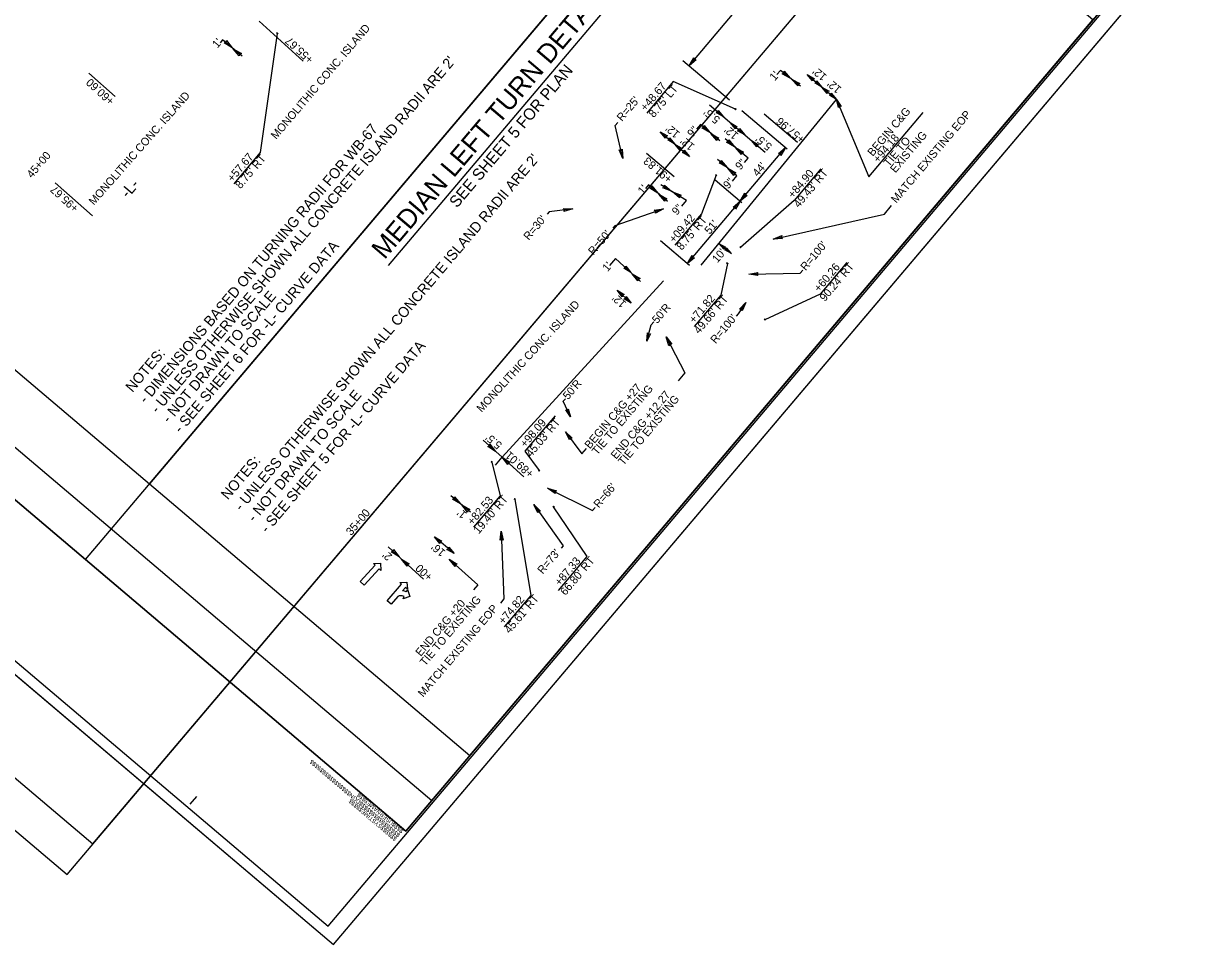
# Model space of a CAD drawing. Extents: x 1763138 to 1764249, y 424045 to 425159.
# Drawn here: x 1763511 to 1764249, y 424122 to 424697 of the extents above; entities that cross this region are included whole.
import ezdxf

# ---------------------------------------------------------------- set-up
doc = ezdxf.new("R2010")
doc.units = 0
for name, color, linetype in [('Default', 7, 'Continuous'), ('Old_Level_11', 7, 'Continuous'), ('Prop Conc 2ft 6in Curb and Gutter', 7, 'Continuous'), ('Prop Dimension Text', 7, 'Continuous'), ('Prop Grid Mask', 7, 'Continuous'), ('Prop Horizontal Alignment Station Label', 7, 'Continuous'), ('Scratch_Level_0', 7, 'Continuous'), ('Sheet Block Revision CELL', 7, 'Continuous'), ('Sheet Clip Boundary CELL', 7, 'Continuous'), ('Sheet Cutting Line CELL', 7, 'Continuous'), ('Sheet Data Field CELL', 7, 'Continuous'), ('Sheet Plan Layout CELL', 7, 'Continuous'), ('Sheet Plot Border Inside CELL', 7, 'Continuous'), ('Sheet Sticker Exception Certification CELL', 7, 'Continuous'), ('Sheet Title CELL', 7, 'Continuous')]:
    doc.layers.add(name, color=color, linetype=linetype)

# ---------------------------------------------------------------- blocks, each defined once
blk = doc.blocks.new('Terminator')
at = {"layer": 'Old_Level_11'}
blk.add_lwpolyline([(-9, 1.55), (0, 0), (-9.05, -1.6), (-7.9, 0)], close=True, dxfattribs=at)

msp = doc.modelspace()

# ---------------------------------------------------------------- linework, layer by layer
at = {"layer": 'Old_Level_11'}
for points in [[(1763637.67, 424686.67), (1763641.21, 424682.13), (1763636.31, 424685.22), (1763637.52, 424685.48)], [(1763645.7, 424677.1), (1763641.97, 424681.49), (1763646.99, 424678.6), (1763645.79, 424678.29)], [(1763994.59, 424658.35), (1763990.74, 424662.62), (1763995.84, 424659.89), (1763994.65, 424659.54)], [(1764003.93, 424661.47), (1764000.6, 424665.44), (1764005.1, 424662.81), (1764004.02, 424662.54)], [(1764006.43, 424661.65), (1764009.76, 424657.68), (1764005.26, 424660.31), (1764006.34, 424660.58)], [(1764013.08, 424653.71), (1764009.76, 424657.68), (1764014.26, 424655.06), (1764013.18, 424654.79)], [(1764015.59, 424653.89), (1764018.91, 424649.93), (1764014.41, 424652.55), (1764015.5, 424652.82)], [(1764020.06, 424644.88), (1764018.91, 424649.93), (1764021.72, 424645.54), (1764020.63, 424645.79)], [(1763944.81, 424643.06), (1763948.14, 424639.09), (1763943.64, 424641.72), (1763944.72, 424641.99)], [(1763955.66, 424631.57), (1763952.33, 424635.54), (1763956.84, 424632.91), (1763955.75, 424632.64)], [(1763912.08, 424625.76), (1763908.76, 424629.73), (1763913.26, 424627.11), (1763912.17, 424626.84)], [(1763914.59, 424625.95), (1763917.91, 424621.98), (1763913.41, 424624.6), (1763914.49, 424624.87)], [(1763944.02, 424624.3), (1763940.32, 424628.71), (1763945.33, 424625.79), (1763944.12, 424625.49)], [(1763958.16, 424631.75), (1763961.49, 424627.78), (1763956.99, 424630.4), (1763958.07, 424630.67)], [(1763921.24, 424618.01), (1763917.91, 424621.98), (1763922.41, 424619.35), (1763921.33, 424619.08)], [(1763923.74, 424618.19), (1763927.07, 424614.22), (1763922.57, 424616.84), (1763923.65, 424617.12)], [(1763959.46, 424615.45), (1763955.77, 424619.86), (1763960.77, 424616.94), (1763959.56, 424616.64)], [(1763969.01, 424620.26), (1763965.69, 424624.22), (1763970.19, 424621.6), (1763969.1, 424621.33)], [(1763946.74, 424611.8), (1763950.44, 424607.39), (1763945.44, 424610.3), (1763946.64, 424610.6)], [(1763954.71, 424602.49), (1763951.01, 424606.9), (1763956.01, 424603.99), (1763954.81, 424603.68)], [(1763911.41, 424596.33), (1763915.75, 424592.56), (1763910.35, 424594.65), (1763911.49, 424595.14)], [(1763911.51, 424586.3), (1763907.88, 424590.77), (1763912.84, 424587.78), (1763911.63, 424587.49)], [(1763920.73, 424588.39), (1763916.39, 424592.17), (1763921.78, 424590.07), (1763920.64, 424589.58)], [(1763905, 424580.71), (1763910.67, 424581.69), (1763905.64, 424578.83), (1763905.98, 424580.02)], [(1763948.45, 424556.45), (1763945.39, 424559.97), (1763949.49, 424557.68), (1763948.52, 424557.42)], [(1763950.08, 424557.16), (1763953.14, 424553.64), (1763949.05, 424555.93), (1763950.02, 424556.19)], [(1763887.26, 424545.85), (1763890.43, 424541.76), (1763886.03, 424544.55), (1763887.13, 424544.78)], [(1763894.7, 424536.54), (1763891.17, 424541.08), (1763896.06, 424537.98), (1763894.84, 424537.73)], [(1763884.91, 424526.69), (1763881.74, 424530.78), (1763886.14, 424527.99), (1763885.04, 424527.76)], [(1763887.42, 424526.78), (1763890.59, 424522.68), (1763886.19, 424525.48), (1763887.29, 424525.71)], [(1763902.56, 424503.59), (1763900.4, 424498.89), (1763900.84, 424504.08), (1763901.55, 424503.22)], [(1763851.27, 424456.68), (1763852.61, 424451.68), (1763849.64, 424455.96), (1763850.73, 424455.75)], [(1763813.4, 424421.83), (1763809.87, 424426.38), (1763814.76, 424423.27), (1763813.54, 424423.01)], [(1763780.19, 424401.65), (1763783.88, 424397.24), (1763778.88, 424400.16), (1763780.09, 424400.46)], [(1763788.35, 424392.19), (1763784.65, 424396.6), (1763789.65, 424393.69), (1763788.45, 424393.39)], [(1763771.04, 424372.64), (1763767.71, 424376.61), (1763772.22, 424373.99), (1763771.13, 424373.72)], [(1763776.6, 424370.24), (1763779.92, 424366.27), (1763775.42, 424368.89), (1763776.5, 424369.17)], [(1763750.5, 424358.31), (1763746.97, 424362.85), (1763751.86, 424359.75), (1763750.64, 424359.5)]]:
    msp.add_lwpolyline(points, close=True, dxfattribs=at)
at = {"layer": 'Prop Conc 2ft 6in Curb and Gutter'}
for p, q in [((1763729.58, 424360.03), (1763733.99, 424360.25)), ((1763730.68, 424359.01), (1763729.58, 424360.03)), ((1763733.99, 424360.25), (1763734.21, 424355.76)), ((1763721.21, 424348.71), (1763730.68, 424359.01)), ((1763733.11, 424356.78), (1763723.63, 424346.47)), ((1763734.21, 424355.76), (1763733.11, 424356.78)), ((1763723.63, 424346.47), (1763721.21, 424348.71)), ((1763738.09, 424336.81), (1763747.14, 424347.22)), ((1763746.01, 424348.21), (1763750.42, 424348.48)), ((1763747.14, 424347.22), (1763746.01, 424348.21)), ((1763749.63, 424345.06), (1763747.76, 424342.91)), ((1763750.76, 424344.07), (1763749.63, 424345.06)), ((1763750.42, 424348.48), (1763750.76, 424344.07)), ((1763744.81, 424339.51), (1763740.58, 424334.65)), ((1763752.18, 424339.53), (1763747.99, 424338.07)), ((1763747.99, 424338.07), (1763748.61, 424339.39)), ((1763750.07, 424342.36), (1763750.72, 424343.72)), ((1763750.72, 424343.72), (1763752.18, 424339.53)), ((1763740.58, 424334.65), (1763738.09, 424336.81))]:
    msp.add_line(p, q, dxfattribs=at)
for centre, radius, start, end in [((1763746.23, 424337.43), 2.52, 88.0631, 124.3751), ((1763746.44, 424335.52), 4.43, 60.69963, 91.55318), ((1763747.88, 424338.49), 4.43, 60.58082, 91.45941)]:
    msp.add_arc(centre, radius, start, end, dxfattribs=at)
at = {"layer": 'Prop Grid Mask'}
msp.add_line((1763738.82, 424546.17), (1763881.32, 424714.38), dxfattribs=at)
at = {"layer": 'Prop Horizontal Alignment Station Label'}
for p, q in [((1763934.24, 424546.32), (1764018.91, 424649.93)), ((1763809.87, 424426.38), (1763910.78, 424536.59)), ((1763805.71, 424421.47), (1763809.87, 424426.38))]:
    msp.add_line(p, q, dxfattribs=at)
at = {"layer": 'Sheet Block Revision CELL'}
for points in [[(1763765.97, 424212), (1764218.44, 424746.11), (1763898.55, 425017.11), (1763837.38, 424944.91), (1763756.7, 425013.26), (1763365.39, 424551.35)], [(1763554.26, 424184.86), (1764006.73, 424718.97), (1763686.84, 424989.97), (1763625.67, 424917.77), (1763544.99, 424986.12), (1763153.68, 424524.22)]]:
    msp.add_lwpolyline(points, close=True, dxfattribs=at)
at = {"layer": 'Sheet Clip Boundary CELL'}
for p, q in [((1763704.59, 424122.13), (1764248.69, 424764.39)), ((1763286.84, 424476.03), (1763704.59, 424122.13))]:
    msp.add_line(p, q, dxfattribs=at)
at = {"layer": 'Sheet Cutting Line CELL'}
for points in [[(1763349.23, 424532.26), (1763749.81, 424192.92), (1764234.6, 424765.18), (1763914.7, 425036.18), (1763837.38, 424944.91), (1763756.7, 425013.26)], [(1763137.52, 424505.12), (1763538.1, 424165.79), (1764022.89, 424738.04), (1763702.99, 425009.04), (1763625.67, 424917.77), (1763544.99, 424986.12)]]:
    msp.add_lwpolyline(points, close=True, dxfattribs=at)
at = {"layer": 'Sheet Data Field CELL'}
for p, q in [((1763615.03, 424209.8), (1763619.08, 424214.57)), ((1763749.81, 424192.92), (1763749.81, 424192.92))]:
    msp.add_line(p, q, dxfattribs=at)
for points in [[(1763834.03, 425104.55), (1763349.23, 424532.28), (1763749.81, 424192.92), (1764234.6, 424765.18)], [(1763749.81, 424192.92), (1763349.23, 424532.26), (1763769.36, 425028.22), (1763826.62, 424979.73), (1763891.27, 425056.04), (1764234.6, 424765.18)]]:
    msp.add_lwpolyline(points, close=True, dxfattribs=at)
at = {"layer": 'Sheet Plan Layout CELL'}
msp.add_lwpolyline([(1763701.16, 424133.55), (1764239.59, 424769.14), (1763837.12, 425110.11), (1763298.67, 424474.52)], close=True, dxfattribs=at)
at = {"layer": 'Sheet Plot Border Inside CELL'}
msp.add_lwpolyline([(1763704.59, 424122.13), (1764248.69, 424764.39), (1763830.94, 425118.29), (1763286.84, 424476.03)], close=True, dxfattribs=at)
at = {"layer": 'Sheet Sticker Exception Certification CELL'}
for points in [[(1763589.54, 424409.85), (1763969.1, 424857.88), (1763768.81, 425027.56), (1763389.25, 424579.52)], [(1763789.83, 424240.17), (1764179.09, 424699.66), (1763978.81, 424869.34), (1763589.54, 424409.85)]]:
    msp.add_lwpolyline(points, close=True, dxfattribs=at)
at = {"layer": 'Sheet Title CELL'}
for p, q in [((1763549.51, 424362.59), (1764034.31, 424934.86)), ((1763926.69, 424671.02), (1764030.12, 424793.1)), ((1763658.14, 424698.8), (1763685.56, 424673.78)), ((1763669.88, 424690.82), (1763669.01, 424691.56)), ((1763669.77, 424691.58), (1763669.12, 424690.8)), ((1763922.85, 424674.27), (1763951.96, 424649.61)), ((1763551.71, 424666.44), (1763568.05, 424651.81)), ((1764000.6, 424665.44), (1764018.91, 424649.93)), ((1763939.4, 424646.5), (1763974.21, 424617)), ((1763956.16, 424643.43), (1763955.3, 424644.16)), ((1763956.06, 424644.18), (1763955.4, 424643.41)), ((1763959.71, 424643.05), (1763987.91, 424619.15)), ((1763973.56, 424640.87), (1763994.39, 424623.22)), ((1763908.76, 424629.73), (1763927.07, 424614.22)), ((1763958.62, 424586.3), (1763987.06, 424619.88)), ((1763900.22, 424616.34), (1763917.47, 424601.73)), ((1763944.14, 424602.17), (1763943.28, 424602.9)), ((1763944.04, 424602.92), (1763943.38, 424602.15)), ((1763530.56, 424597.85), (1763553.92, 424577.28)), ((1763959.64, 424585.44), (1763942.92, 424599.6)), ((1763925.65, 424547.39), (1763958.62, 424586.3)), ((1763926.94, 424546.3), (1763908.85, 424561.63)), ((1763945.39, 424559.97), (1763953.14, 424553.64)), ((1763959.34, 424557.17), (1763958.47, 424557.9)), ((1763959.23, 424557.92), (1763958.57, 424557.14)), ((1763951.06, 424547.04), (1763950.19, 424547.77)), ((1763950.95, 424547.79), (1763950.29, 424547.01)), ((1763890.59, 424522.68), (1763881.74, 424530.78)), ((1763974.55, 424511.99), (1763973.68, 424512.72)), ((1763974.44, 424512.74), (1763973.79, 424511.97)), ((1763809.87, 424426.38), (1763798.1, 424437.16)), ((1763823.46, 424414.27), (1763809.87, 424426.38)), ((1763803.86, 424423.04), (1763802.99, 424423.77)), ((1763803.75, 424423.79), (1763803.09, 424423.01)), ((1763833.41, 424417.7), (1763832.54, 424418.43)), ((1763833.3, 424418.45), (1763832.65, 424417.67)), ((1763818.25, 424399.81), (1763817.39, 424400.54)), ((1763818.15, 424400.56), (1763817.49, 424399.78)), ((1763842.48, 424395.13), (1763841.61, 424395.86)), ((1763842.37, 424395.88), (1763841.71, 424395.11)), ((1763779.92, 424366.27), (1763767.71, 424376.61)), ((1763738.73, 424370.4), (1763760.8, 424350.19))]:
    msp.add_line(p, q, dxfattribs=at)
for points in [[(1763647.42, 424676.93), (1763635.24, 424687.11), (1763633.77, 424685.37)], [(1763669.45, 424691.19), (1763658.82, 424616.84), (1763642.2, 424597.22)], [(1763996.32, 424658.23), (1763983.85, 424668.05), (1763981.62, 424665.41)], [(1763955.73, 424643.8), (1763916.85, 424661.04), (1763900.23, 424641.43)], [(1764018.91, 424649.93), (1764039.02, 424601.53), (1764073.04, 424641.69)], [(1763885.34, 424613.05), (1763880.53, 424633.59), (1763882.11, 424635.45)], [(1763945.85, 424624.03), (1763933.82, 424634.22), (1763931.39, 424631.34)], [(1763961.26, 424610.45), (1763963.61, 424613.22), (1763949.26, 424625.37)], [(1763953.93, 424598.98), (1763956.62, 424602.15), (1763944.51, 424612.41)], [(1764008.95, 424606.51), (1763992.33, 424586.89), (1763958.9, 424557.53)], [(1763913.23, 424586.1), (1763901.27, 424596.53), (1763899.42, 424594.35)], [(1763922.18, 424583.29), (1763925.18, 424586.83), (1763909.1, 424596.59)], [(1763943.71, 424602.54), (1763934.49, 424578.46), (1763917.87, 424558.84)], [(1763854.05, 424581.65), (1763839.32, 424579.65), (1763838.08, 424578.19)], [(1763910.67, 424581.69), (1763880.29, 424570.89), (1763879.05, 424569.42)], [(1763979.3, 424562.67), (1764048.75, 424578.33), (1764053.23, 424583.63)], [(1763896.41, 424536.29), (1763880.68, 424550.65), (1763876.98, 424546.28)], [(1763950.63, 424547.41), (1763946.61, 424527.69), (1763929.99, 424508.07)], [(1764025.22, 424547.99), (1764008.6, 424528.37), (1763974.12, 424512.36)], [(1763964.08, 424540.79), (1763996.19, 424541.4), (1763997.77, 424543.26)], [(1763962.24, 424523.06), (1763957.45, 424516.09), (1763956.21, 424514.63)], [(1763900.4, 424498.89), (1763903.1, 424509.07), (1763904.76, 424511.03)], [(1763912.35, 424501.56), (1763924.13, 424479.11), (1763919.97, 424474.2)], [(1763852.61, 424451.68), (1763848.11, 424461.41), (1763849.45, 424462.99)], [(1763842.97, 424452.32), (1763824.19, 424430.15), (1763832.98, 424418.07)], [(1763849.44, 424442.39), (1763859.77, 424428.62), (1763862.61, 424431.97)], [(1763803.42, 424423.4), (1763808.59, 424402.29), (1763791.97, 424382.67)], [(1763838.35, 424407.12), (1763866.44, 424393.14), (1763868.02, 424395)], [(1763790.07, 424392.02), (1763777.95, 424402.26)], [(1763817.82, 424400.18), (1763827.87, 424340.13), (1763811.25, 424320.51)], [(1763829.75, 424396.88), (1763848.08, 424371.08), (1763846.85, 424369.62)], [(1763845.18, 424343.15), (1763863.13, 424364.33), (1763842.04, 424395.5)], [(1763809.35, 424380.24), (1763811.04, 424337.89), (1763808.83, 424335.28)], [(1763776.92, 424362.71), (1763794.68, 424346.75), (1763792.01, 424343.59)]]:
    msp.add_lwpolyline(points, dxfattribs=at)

# ---------------------------------------------------------------- block references
at = {"layer": 'Default'}
for p, xscale, yscale, rotation in [((1763926.69, 424671.02), 0.6300000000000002, 0.6299999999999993, -130.26989656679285), ((1763989.96, 424663.24), 0.6300000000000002, 0.6299999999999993, -38.216341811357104), ((1763939.75, 424629.19), 0.6300000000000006, 0.6299999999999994, -40.269896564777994), ((1763885.34, 424613.05), 0.6300000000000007, 0.6299999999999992, -76.80801773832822), ((1763955.19, 424620.35), 0.6300000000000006, 0.6299999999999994, -40.269896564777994), ((1763987.06, 424619.88), 0.6300000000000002, 0.6299999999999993, 49.73010343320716), ((1763907.13, 424591.42), 0.6300000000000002, 0.6299999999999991, -41.09557866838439), ((1763958.62, 424586.3), 0.6300000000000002, 0.6299999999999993, -130.26989656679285), ((1763854.05, 424581.65), 0.6299999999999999, 0.6299999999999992, 7.706806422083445), ((1763958.62, 424586.3), 0.6300000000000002, 0.6299999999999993, 49.73010343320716), ((1763979.3, 424562.67), 0.6300000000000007, 0.6299999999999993, -167.28779310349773), ((1763925.65, 424547.39), 0.6300000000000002, 0.6299999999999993, -130.26989656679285), ((1763964.08, 424540.79), 0.6300000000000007, 0.6299999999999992, -178.90669150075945), ((1763962.24, 424523.06), 0.6300000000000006, 0.6299999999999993, 55.467364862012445), ((1763912.35, 424501.56), 0.630000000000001, 0.6299999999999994, 117.68870627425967), ((1763849.44, 424442.39), 0.6300000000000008, 0.6299999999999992, 126.89575304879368), ((1763805.82, 424430.09), 0.6300000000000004, 0.6299999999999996, -42.4765986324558), ((1763838.35, 424407.12), 0.6300000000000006, 0.6299999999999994, 153.5465740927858), ((1763829.75, 424396.88), 0.6300000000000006, 0.6299999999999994, 125.40671690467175), ((1763809.35, 424380.24), 0.6300000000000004, 0.6299999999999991, 92.2799832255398), ((1763745.49, 424364.2), 0.6300000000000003, 0.629999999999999, -42.391811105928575), ((1763776.92, 424362.71), 0.6300000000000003, 0.6299999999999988, 138.05302793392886)]:
    msp.add_blockref('Terminator', p, dxfattribs=dict(at, xscale=xscale, yscale=yscale, rotation=rotation))

# ---------------------------------------------------------------- texts
at = {"layer": 'Prop Dimension Text'}
for s, height, rotation, p in [('MEDIAN LEFT TURN DETAIL', 12, 49.7301, (1763736.44, 424549.47)), ('MONOLITHIC CONC. ISLAND', 5, 49.7301, (1763668.74, 424624.66)), ("1'", 5, 49.7301, (1763632.06, 424681.62)), ('+55.67', 5, 137.61701, (1763692.47, 424675.49)), ("- UNLESS OTHERWISE SHOWN ALL CONCRETE ISLAND RADII ARE 2'", 6.5, 49.7301, (1763594.61, 424453.31)), ('SEE SHEET 5 FOR PLAN', 7.2, 49.7301, (1763781.7, 424581.78)), ("12'", 5, 139.7301, (1764013.22, 424664.73)), ('+60.60', 5, 137.61701, (1763568.05, 424649.56)), ("1'", 5, 49.7301, (1763980.29, 424661.15)), ('MONOLITHIC CONC. ISLAND', 5, 48.63875, (1763554.88, 424583.52)), ('+48.67', 5, 49.7301, (1763899.55, 424642.26)), ("8.75' LT", 5, 49.7301, (1763904.67, 424638.17)), ("12'", 5, 139.7301, (1764022.37, 424656.97)), ("R=25'", 5, 49.7301, (1763884.84, 424635.83)), ("5.5'", 5, 139.7301, (1763946.51, 424638.03)), ('BEGIN C&G', 5, 49.7301, (1764041.48, 424614.04)), ('MATCH EXISTING EOP', 5, 49.7301, (1764056.18, 424584.83)), ('- DIMENSIONS BASED ON TURNING RADII FOR WB-67', 6.5, 49.7301, (1763587.26, 424459.53)), ("12'", 5, 139.7301, (1763921.37, 424629.02)), ('9"', 5, 47.22732, (1763928.69, 424625.9)), ("12'", 5, 139.7301, (1763958.02, 424628.19)), ('+57.96', 5, 139.7301, (1763999.54, 424625.83)), ("12'", 5, 139.7301, (1763930.53, 424621.26)), ("5.5'", 5, 139.7301, (1763979.01, 424621.3)), ('+94.18', 5, 49.7301, (1764044.99, 424609.95)), ('TIE TO', 5, 49.7301, (1764051.54, 424607.56)), ('EXISTING', 5, 49.7301, (1764055.64, 424603.67)), ('+57.67', 5, 49.7301, (1763641.53, 424598.06)), ("8.75' RT", 5, 49.7301, (1763646.46, 424593.74)), ("- UNLESS OTHERWISE SHOWN ALL CONCRETE ISLAND RADII ARE 2'", 6.5, 49.7301, (1763646.94, 424392.34)), ('+91.83', 5, 139.7301, (1763916.63, 424601.04)), ('9"', 5, 47.22732, (1763958.67, 424605.45)), ("44'", 5, 49.7301, (1763969.64, 424601.35)), ('+84.90', 5, 49.7301, (1763991.73, 424587.82)), ("49.43' RT", 5, 49.7301, (1763995.31, 424581.9)), ("1'", 5, 49.7301, (1763897.88, 424590.13)), ('9"', 5, 47.22732, (1763951.13, 424593.62)), ('+95.67', 5, 137.61701, (1763545.72, 424582.63)), ('9"', 5, 47.22732, (1763919.04, 424577.2)), ("R=30'", 5, 49.7301, (1763826.56, 424561.61)), ('+09.42', 5, 49.7301, (1763917.45, 424559.97)), ("8.75' RT", 5, 49.7301, (1763922.13, 424555.35)), ("51'", 5, 49.7301, (1763939.6, 424565.28)), ("R=50'", 5, 49.7301, (1763866.96, 424552.31)), ('- SEE SHEET 6 FOR -L- CURVE DATA', 6.5, 49.7301, (1763609.12, 424441.01)), ("R=100'", 5, 49.7301, (1763999.61, 424542.59)), ("10'", 5, 49.7301, (1763944.41, 424547.47)), ("1'", 5, 49.7301, (1763875.82, 424542.01)), ('+60.26', 5, 49.7301, (1764008.02, 424529.31)), ("90.24' RT", 5, 49.7301, (1764011.58, 424523.38)), ('- NOT DRAWN TO SCALE', 6.5, 49.7301, (1763601.74, 424447.27)), ('MONOLITHIC CONC. ISLAND', 5, 47.61162, (1763797.15, 424454.14)), ("12'", 5, 137.5234, (1763887.9, 424522.87)), ("50'R", 5, 49.7301, (1763906.83, 424509.52)), ('+71.82', 5, 49.7301, (1763929.95, 424509.66)), ("49.66' RT", 5, 49.7301, (1763932.96, 424503.08)), ("R=100'", 5, 49.7301, (1763943.31, 424497.03)), ('NOTES:', 6.5, 49.7301, (1763578.98, 424466.55)), ('- SEE SHEET 5 FOR -L- CURVE DATA', 6.5, 49.7301, (1763663.16, 424378.6)), ("50'R", 5, 49.7301, (1763851.15, 424461.98)), ('BEGIN C&G +27', 5, 49.7301, (1763864.74, 424431.29)), ('TIE TO EXISTING', 5, 49.7301, (1763869.31, 424427.41)), ('- NOT DRAWN TO SCALE', 6.5, 49.7301, (1763655.08, 424385.44)), ('END C&G +12.27', 5, 49.7301, (1763881.12, 424424.84)), ('TIE TO EXISTING', 5, 49.7301, (1763885.7, 424420.96)), ('+98.09', 5, 49.7301, (1763824.45, 424432.08)), ("45.03' RT", 5, 49.7301, (1763828, 424426.13)), ("5.5'", 5, 139.7301, (1763810.26, 424434.72)), ('NOTES:', 6.5, 49.7301, (1763638.61, 424399.4)), ('+89.01', 5, 138.54276, (1763830.11, 424416.81)), ("R=66'", 5, 49.7301, (1763870.35, 424394.36)), ('+82.53', 5, 49.7301, (1763791.44, 424383.68)), ("19.40' RT", 5, 49.7301, (1763795.33, 424378.13)), ("1'", 5, 139.7301, (1763788.19, 424391.33)), ("2'", 5, 139.7301, (1763741.64, 424365.1)), ("16'", 5, 139.7301, (1763774.97, 424367.58)), ("R=73'", 5, 49.7301, (1763835.24, 424353.13)), ('+87.33', 5, 49.7301, (1763845.98, 424345.72)), ("66.80' RT", 5, 49.7301, (1763849.48, 424339.72)), ('END C&G +20', 5, 49.7301, (1763759.06, 424301.66)), ('TIE TO EXISTING', 5, 49.7301, (1763761.82, 424295.64)), ('+74.82', 5, 49.7301, (1763810.83, 424321.64)), ("45.61' RT", 5, 49.7301, (1763814.62, 424315.97)), ('MATCH EXISTING EOP', 5, 49.7301, (1763760.56, 424276.22))]:
    msp.add_text(s, height=height, rotation=rotation, dxfattribs=at).set_placement(p)
at = {"layer": 'Scratch_Level_0'}
for s, height, p in [('45+00', 5, (1763516.16, 424600.42)), ('-L-', 7, (1763576.15, 424587.81)), ('35+00', 5, (1763715.65, 424377.16))]:
    msp.add_text(s, height=height, rotation=49.7301, dxfattribs=at).set_placement(p)
at = {"layer": 'Sheet Data Field CELL'}
for s, p in [('$$$$$$$$$$$$$$$$DGN$$$$$$$$$$$$$$$$', (1763746.44, 424190.77)), ('$$$$$$SYSTIME$$$$$', (1763744.48, 424188.45)), ('$$$$USERNAME$$$$', (1763748.55, 424193.27))]:
    msp.add_text(s, height=2.625, rotation=139.73011, dxfattribs=at).set_placement(p)
at = {"layer": 'Sheet Title CELL'}
msp.add_text('+00', height=5, rotation=136.6532, dxfattribs=at).set_placement((1763766.92, 424352.3))

doc.saveas('drawing.dxf')
